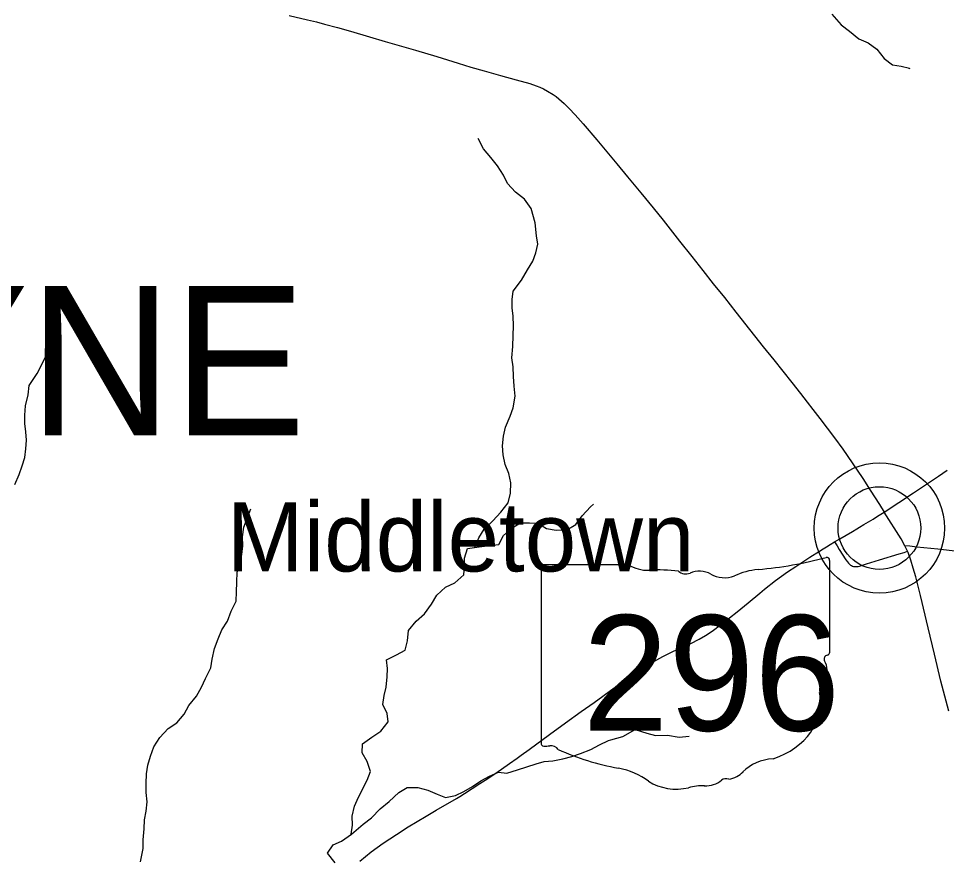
# Model space of a CAD drawing. Extents: x 0 to 1101, y 0 to 440.
# Drawn here: x 847.022 to 848.082, y 372.865 to 373.824 of the extents above; entities that cross this region are included whole.
import ezdxf

# ---------------------------------------------------------------- set-up
doc = ezdxf.new("R2010")
doc.units = 0
for name, color, linetype in [('GM_X_County_Road', 7, 'Continuous'), ('GM_X_Minor_River', 7, 'Continuous'), ('GM_X_State_Location', 7, 'Continuous'), ('GM_X_State_Route', 7, 'Continuous'), ('GM_X_State_Shield', 7, 'Continuous'), ('GM_X_Township_Road', 7, 'Continuous'), ('GM_X_Township_Text', 7, 'Continuous'), ('GM_X_Unincorporated', 7, 'Continuous'), ('GM_X_Unincorporated_Location', 7, 'Continuous'), ('GM_X_Unincorporated_Text', 7, 'Continuous')]:
    doc.layers.add(name, color=color, linetype=linetype)

msp = doc.modelspace()

# ---------------------------------------------------------------- linework, layer by layer
at = {"layer": 'GM_X_County_Road'}
msp.add_lwpolyline([(848.1077, 373.214), (848.0719, 373.2181), (848.0479, 373.2205), (848.04, 373.2215), (848.0343, 373.2222)], dxfattribs=at)
at = {"layer": 'GM_X_Minor_River'}
for points in [[(847.9509, 373.8293), (847.9615, 373.8171), (847.971, 373.8099), (847.9817, 373.8012), (847.9923, 373.7966), (848.0021, 373.7891), (848.0105, 373.7788), (848.02, 373.7712), (848.0302, 373.7697), (848.0397, 373.7675), (848.039, 373.7663)], [(847.543, 373.2203), (847.5477, 373.2312), (847.5539, 373.241), (847.5635, 373.2507), (847.5727, 373.2605), (847.5812, 373.271), (847.5839, 373.2824), (847.5844, 373.2941), (847.5819, 373.3048), (847.5778, 373.3151), (847.5756, 373.3261), (847.5746, 373.3363), (847.5758, 373.3473), (847.5782, 373.3575), (847.5836, 373.37), (847.5868, 373.3795), (847.5892, 373.3931), (847.5881, 373.4045), (847.5871, 373.4155), (847.5868, 373.4265), (847.5854, 373.4368), (847.5867, 373.4496), (847.5868, 373.4622), (847.5873, 373.4735), (847.587, 373.4842), (847.5856, 373.4937), (847.5856, 373.5032), (847.5869, 373.513), (847.5965, 373.5255), (847.6031, 373.5372), (847.6093, 373.547), (847.6128, 373.5568), (847.6152, 373.5667), (847.6137, 373.5762), (847.612, 373.591), (847.6076, 373.6074), (847.5997, 373.6181), (847.5895, 373.6261), (847.5804, 373.6357), (847.5759, 373.6453), (847.5692, 373.656), (847.5613, 373.6655), (847.553, 373.6755), (847.547, 373.6873)], [(847.0179, 373.2922), (847.0229, 373.3036), (847.0261, 373.3134), (847.0292, 373.3229), (847.0304, 373.3327), (847.0309, 373.3429), (847.0303, 373.3524), (847.0292, 373.3619), (847.0293, 373.3714), (847.0301, 373.382), (847.0329, 373.3945), (847.0342, 373.4051), (847.0434, 373.4187), (847.0528, 373.4376), (847.0528, 373.4471), (847.0564, 373.4573), (847.0568, 373.4668), (847.058, 373.4671)], [(847.278, 373.2219), (847.2777, 373.2322), (847.2794, 373.2435), (847.2833, 373.2545), (847.2872, 373.2643)], [(847.402, 372.8929), (847.4033, 372.9031), (847.403, 372.9134), (847.4058, 372.9247), (847.4101, 372.9349), (847.4202, 372.9545), (847.4241, 372.9643), (847.42, 372.9757), (847.4144, 372.9856), (847.4149, 372.9959), (847.4256, 373.0037), (847.4359, 373.0105), (847.444, 373.021), (847.443, 373.0305), (847.4381, 373.0408), (847.4394, 373.051), (847.4417, 373.0608), (847.443, 373.0726), (847.4435, 373.082), (847.4424, 373.0919), (847.4535, 373.0975), (847.4635, 373.1031), (847.4662, 373.1136), (847.4675, 373.1254), (847.476, 373.1359), (847.4856, 373.1445), (847.4937, 373.1555), (847.4998, 373.1656), (847.5095, 373.175), (847.5202, 373.1799), (847.5305, 373.1889), (847.5314, 373.1983), (847.5315, 373.2078), (847.5346, 373.2191), (847.548, 373.2209), (847.5602, 373.2223), (847.5704, 373.2237), (847.5759, 373.2339), (847.5859, 373.2426), (847.5954, 373.2485), (847.6057, 373.2484), (847.6152, 373.248), (847.6251, 373.2418), (847.6361, 373.2398), (847.6483, 373.2405), (847.6586, 373.2464), (847.6659, 373.2562), (847.6752, 373.2667), (847.6786, 373.2697)], [(847.1611, 372.861), (847.1643, 372.8765), (847.1644, 372.8864), (847.1653, 372.8989), (847.1658, 372.9091), (847.1678, 372.919), (847.169, 372.9296), (847.1676, 372.9402), (847.1677, 372.9508), (847.1682, 372.9618), (847.1698, 372.9716), (847.1726, 372.9818), (847.1765, 372.9924), (847.1834, 373.003), (847.193, 373.0135), (847.2026, 373.0198), (847.2111, 373.03), (847.2165, 373.0398), (847.2254, 373.0503), (847.2308, 373.0605), (847.2355, 373.0707), (847.2417, 373.0828), (847.2433, 373.0926), (847.2457, 373.1047), (847.25, 373.1157), (847.2543, 373.1262), (847.2608, 373.136), (847.2648, 373.1474), (847.2706, 373.1587), (847.2711, 373.1697), (847.2712, 373.1807), (847.2717, 373.192), (847.2748, 373.2022), (847.2772, 373.2121), (847.278, 373.2219)], [(847.6985, 373.0004), (847.7123, 373.0044), (847.7261, 373.0125), (847.7396, 373.0081), (847.7494, 373.0053), (847.763, 373.0058), (847.7766, 373.0037), (847.788, 373.0047)], [(847.4454, 372.93), (847.4562, 372.9402), (847.4658, 372.9461), (847.478, 372.946), (847.4894, 372.9429), (847.5, 372.9386), (847.5095, 372.9347), (847.5209, 372.9369), (847.5305, 372.9414), (847.5404, 372.9473), (847.55, 372.9537), (847.5599, 372.9589), (847.5703, 372.9637), (847.5798, 372.9625), (847.592, 372.9662), (847.6027, 372.9695), (847.613, 372.9732), (847.6225, 372.9758), (847.6324, 372.9764), (847.6435, 372.979), (847.6538, 372.9815), (847.6637, 372.9848), (847.6756, 372.9893), (847.6855, 372.9949), (847.6959, 372.9997), (847.6985, 373.0004)], [(847.3835, 372.8601), (847.3748, 372.8712), (847.3814, 372.8806), (847.391, 372.8847), (847.4021, 372.8929), (847.4155, 372.9042), (847.4251, 372.9116), (847.4351, 372.9218), (847.4454, 372.93)]]:
    msp.add_lwpolyline(points, dxfattribs=at)
at = {"layer": 'GM_X_State_Route'}
for points in [[(847.331, 373.8279), (847.3522, 373.8229), (847.3623, 373.8205), (847.3715, 373.818), (847.3863, 373.8139), (847.4012, 373.8098), (847.4229, 373.8035), (847.4408, 373.7982), (847.4754, 373.788), (847.4998, 373.7808), (847.5242, 373.7733), (847.5387, 373.7689), (847.5539, 373.7645), (847.5726, 373.7592), (847.5904, 373.7542), (847.606, 373.7499), (847.6133, 373.7475), (847.6174, 373.7459), (847.6215, 373.7439), (847.6262, 373.7415), (847.6326, 373.7375), (847.6361, 373.7352), (847.6391, 373.7327), (847.6452, 373.7273), (847.651, 373.7216), (847.6579, 373.7143), (847.667, 373.7041), (847.6826, 373.6856), (847.7052, 373.6583), (847.7175, 373.6435), (847.7326, 373.6253), (847.7469, 373.6081), (847.7581, 373.594), (847.777, 373.5701), (847.7908, 373.5525), (847.8035, 373.5364), (847.8155, 373.5214), (847.8284, 373.5055), (847.8414, 373.4889), (847.8625, 373.462), (847.8725, 373.4493), (847.8846, 373.4343), (847.905, 373.4086), (847.915, 373.3959), (847.9227, 373.3862), (847.9292, 373.3779), (847.9371, 373.3675), (847.954, 373.3453), (847.9635, 373.3323), (847.9742, 373.317), (847.9862, 373.2989), (847.9945, 373.2857), (848.0053, 373.2694), (848.0108, 373.2605)], [(848.0108, 373.2605), (848.0272, 373.2714), (848.0441, 373.2826), (848.0728, 373.3017), (848.0827, 373.3085)], [(847.4118, 372.8621), (847.4249, 372.8726), (847.4385, 372.8825), (847.4535, 372.8925), (847.4671, 372.9012), (847.4874, 372.9133), (847.4991, 372.9202), (847.5222, 372.9337), (847.5259, 372.9359), (847.5312, 372.9392), (847.549, 372.9505), (847.5578, 372.9563), (847.5696, 372.9644), (847.5737, 372.9671), (847.5828, 372.9735), (847.5914, 372.9796), (847.5959, 372.983), (847.605, 372.9895), (847.6285, 373.0066), (847.6466, 373.0198), (847.6647, 373.0328), (847.6795, 373.0431), (847.6895, 373.0504), (847.698, 373.0567), (847.7125, 373.0673), (847.7217, 373.0737), (847.7361, 373.0833), (847.7474, 373.09), (847.7578, 373.0956), (847.7701, 373.1016), (847.7898, 373.1107), (847.7992, 373.1155), (847.8067, 373.1198), (847.814, 373.1245), (847.8254, 373.133), (847.8429, 373.1468), (847.8554, 373.157), (847.8687, 373.1681), (847.874, 373.1725), (847.8867, 373.1825), (847.9003, 373.1924), (847.9096, 373.1986), (847.9257, 373.2091), (847.9368, 373.2161), (847.941, 373.2187), (847.9446, 373.2211), (847.9489, 373.2236), (847.9539, 373.2265), (847.9601, 373.2302), (847.9746, 373.2386), (847.9794, 373.2415), (847.9826, 373.2433), (847.9873, 373.2463), (847.9979, 373.2526), (848.0032, 373.2559), (848.0108, 373.2605)]]:
    msp.add_lwpolyline(points, dxfattribs=at)
at = {"layer": 'GM_X_State_Shield'}
for p, q in [((847.6188, 373.197), (847.6188, 372.9969)), ((847.7186, 373.2004), (847.6221, 373.2004)), ((847.9484, 373.1007), (847.9484, 373.2054)), ((847.9484, 373.1007), (847.9484, 373.1007))]:
    msp.add_line(p, q, dxfattribs=at)
for centre, major_axis, start_param, end_param in [((847.831, 373.4733), (0.3495, 0), 4.814394, 5.042369), ((847.9447, 373.2058), (0.00367, 0), 6.141152, 7.989035), ((847.6226, 373.1974), (0.00382, 0), 1.712693, 3.28349), ((847.7416, 373.2237), (0.037, 0), 4.042523, 4.731795), ((847.7539, 373.0881), (0.133, 0), 1.404758, 1.657858), ((847.784, 373.1985), (0.0107, 0), 3.836095, 5.185415), ((847.7997, 373.1753), (0.0222, 0), 0.950623, 2.079405), ((847.8284, 373.207), (0.0267, 0), 4.081561, 5.145723), ((847.8756, 373.1393), (0.0703, 0), 1.699011, 2.107814), ((847.9476, 373.093), (0.00568, 0), 1.883978, 3.671073), ((847.9445, 373.1003), (0.00393, 0), 5.05454, 6.418171), ((847.9114, 373.0798), (0.0341, 0), 5.934695, 6.695948), ((847.9616, 373.0569), (0.0248, 0), 2.387724, 3.262537), ((847.8506, 373.0436), (0.0874, 0), 5.101752, 6.440018), ((847.6226, 372.9964), (0.00385, 0), 3.00124, 4.508301), ((847.6232, 373.0169), (0.0294, 0), 4.665946, 4.897461), ((847.6292, 372.9853), (0.0106, 0), 0.519207, 1.627899), ((847.7631, 373.1651), (0.2524, 0), 4.195997, 4.488961), ((847.8874, 372.9407), (0.0479, 0), 1.647645, 2.488434), ((847.6878, 372.907), (0.079, 0), 0.823519, 1.323587), ((847.8268, 372.9775), (0.0282, 0), 4.937069, 5.64225), ((847.7732, 372.9843), (0.0501, 0), 4.026481, 4.996735), ((847.8058, 372.9693), (0.0267, 0), 4.691044, 5.507374), ((847.83, 372.95), (0.00752, 0), 1.147584, 2.315152), ((847.8022, 372.9151), (0.0412, 0), 1.495662, 1.94098)]:
    msp.add_ellipse(centre, major_axis=major_axis, ratio=0.8, start_param=start_param, end_param=end_param, dxfattribs=at)
at = {"layer": 'GM_X_Township_Road'}
for points in [[(848.0343, 373.2222), (848.0299, 373.2299), (848.0108, 373.2605)], [(847.9539, 373.2265), (847.9568, 373.2219), (847.9592, 373.218), (847.967, 373.2061), (847.9686, 373.2038), (847.97, 373.2022), (847.9711, 373.2011), (847.9723, 373.2001), (847.9732, 373.1995), (847.9744, 373.199), (847.9756, 373.1986), (847.9768, 373.1984), (847.9781, 373.1983), (847.9792, 373.1984), (847.9808, 373.1986), (847.9823, 373.1989), (847.9906, 373.2016), (848.0054, 373.206), (848.0279, 373.2128), (848.0336, 373.2146), (848.0373, 373.2159)], [(848.0373, 373.2159), (848.0351, 373.2207), (848.0343, 373.2222)], [(848.0844, 373.0333), (848.0754, 373.0675), (848.068, 373.0983), (848.0607, 373.1285), (848.052, 373.1654), (848.0467, 373.1865), (848.0439, 373.1965), (848.0411, 373.2056), (848.038, 373.2144), (848.0373, 373.2159)]]:
    msp.add_lwpolyline(points, dxfattribs=at)
at = {"layer": 'GM_X_Unincorporated'}
for radius in [0.0744, 0.0472]:
    msp.add_circle((848.0052, 373.2424), radius, dxfattribs=at)
at = {"layer": 'GM_X_Unincorporated_Location'}
msp.add_line((848.0052, 373.2424), (848.0052, 373.2424), dxfattribs=at)

# ---------------------------------------------------------------- texts
at = {"layer": 'GM_X_State_Location'}
for s in ['s', 'r']:
    msp.add_text(s, height=0.000189, dxfattribs=at).set_placement((847.7799, 373.0836))
msp.add_text('296', height=0.000189, rotation=0, dxfattribs=at).set_placement((847.7131, 373.0698))
at = {"layer": 'GM_X_State_Shield'}
msp.add_text('296', height=0.13184, dxfattribs=at).set_placement((847.6662, 373.011))
at = {"layer": 'GM_X_Township_Text'}
msp.add_text('WAYNE', height=0.17045, rotation=0, dxfattribs=at).set_placement((846.5143, 373.3483))
at = {"layer": 'GM_X_Unincorporated_Text'}
msp.add_text('Middletown', height=0.07898, rotation=0, dxfattribs=at).set_placement((847.2597, 373.1928))

doc.saveas('drawing.dxf')
